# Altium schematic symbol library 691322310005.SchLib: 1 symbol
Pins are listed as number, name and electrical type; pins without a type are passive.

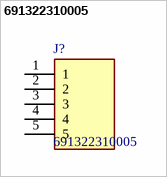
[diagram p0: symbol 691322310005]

## 691322310005
designator J?
WR-TBL Terminal block - PCB Header - THT Serie 322 - 3,81mm pitch - Monoblock THT - Green - Horizontal PCB Header 05p; Manufacturer_Name: Wurth Elektronik; Geometry.Height: 7.2mm
footprint SHDRRA5W80P0X381_1X5_2024X920X720P
pins: 1, 2, 3, 4, 5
